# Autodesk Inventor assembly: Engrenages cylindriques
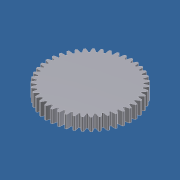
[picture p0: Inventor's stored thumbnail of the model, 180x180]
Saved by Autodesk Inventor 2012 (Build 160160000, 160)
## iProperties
Created: 2011-10
Part Number: Engrenages cylindriques
Document SubType Name: Assembly
Designer: Laur
ClientObjectVersion: 1
Author: Laur
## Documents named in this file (2)
- D:\Formulaire\Sujet CIM 4 Poissy\Modélisation_7970_shimano\roue droite de vis arbrée\Design Accelerator\Engrenages cylindriques2.iam
- D:\Formulaire\Sujet CIM 4 Poissy\Modélisation_7970_shimano\roue droite de vis arbrée\Design Accelerator\Engrenage cylindrique21.ipt
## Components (1 placed, 1 different names)
1. Engrenage cylindrique2:1
